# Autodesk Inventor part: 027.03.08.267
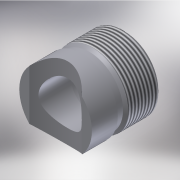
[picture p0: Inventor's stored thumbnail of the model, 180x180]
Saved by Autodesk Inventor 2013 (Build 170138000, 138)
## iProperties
Shininess: 25.0
Length Units: 11269
Angle Units: 11279
Time Units: 11290
Mass Units: 11283
Length Display Precision: 3
Angle Display Precision: 2
Created: 2001-08
Part Number: 027.03.08.267
Material: Steel, Mild
Document SubType Name: Modeling
Designer: SOleg
Density: 1 g/cm^3
Density: 0.0
Volumn: 0.0
Area: 0.0
PropertySet Name: Model Information
Control State: 0
Master: False
Checked Out: True
Checked Out Date: 2008-10-15
Last Check In Date: 2008-10-15
Author: SOleg
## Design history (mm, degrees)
sketch "Sketch1"
  geometry: L1 (151.133, 104.399)-(151.133, 119.399); L2 (151.133, 119.399)-(152.633, 119.399); L3 (152.633, 119.399)-(152.633, 123.899); L4 (152.633, 123.899)-(151.133, 125.399); L5 (151.133, 125.399)-(151.133, 144.399); L6 (151.133, 144.399)-(172.133, 144.399); L7 (172.133, 144.399)-(172.133, 104.399); L8 (172.133, 104.399)-(151.133, 104.399); L9 (172.133, 144.399)-(172.133, 104.399); 1 further point
  constraints: 18 end point, 1 other
  dimensions: "d1" = 40 distance of L6.end L7.end; "d3" = 21 distance of L5.end L6.end; "d5" = 21 distance of L7.end L1.start; "d7" = 25 vertical distance of L5.end L2.end; "d9" = 4.5 distance of L2.end L3.end; "d11" = 135 deg angle of L4 L3; "d13" = 19.5 horizontal distance of L3.end L6.end; "d31" = 172.13342 distance from line of point (0, 0) L7
revolve "RevolutionFull1" sketch "Sketch1" stored, may be unused: angle "d14" = 360 deg
chamfer "Chamfer1" distance "d15" = 1.6; stored, may be unused: second distance "d16" = 1.6, angle "d34" = 45 deg
sketch "Sketch2"
  geometry: C1 r 21 at (0, 0) reference
hole "Hole1" sketch "Sketch2" diameter "d18" = 25; stored, may be unused: countersink angle "d22" = 24 deg, drill point angle "d24" = 120 deg; dims "d19" = 6, "d20" = 33, "d21" = 2, "d23" = 8
sketch "Sketch3"
  geometry: L1 (193.133, 104.399)-(151.133, 104.399) reference; C1 r 20 at (172.133, 91.399)
  constraints: 1 centre point
  dimensions: "d26" = 40 diameter of C1; "d32" = 21 horizontal distance of C1.centre L1.end; "d33" = 7 distance edge to line of C1 L1
extrude "ExtrusionMidplane1" cut sketch "Sketch3" stored distance "d27" = 50; taper "d28" = 0 deg
thread "Thread1" dims "d29" = 10, "d30" = 0
body "Solid1"
other parameters: "d2" = 21 (derived), "d4" = 21 (derived), "d6" = 25 (derived), "d8" = 4.5 (derived), "d10" = 135 deg (derived), "d12" = 19.5 (derived), "d17" = 0
